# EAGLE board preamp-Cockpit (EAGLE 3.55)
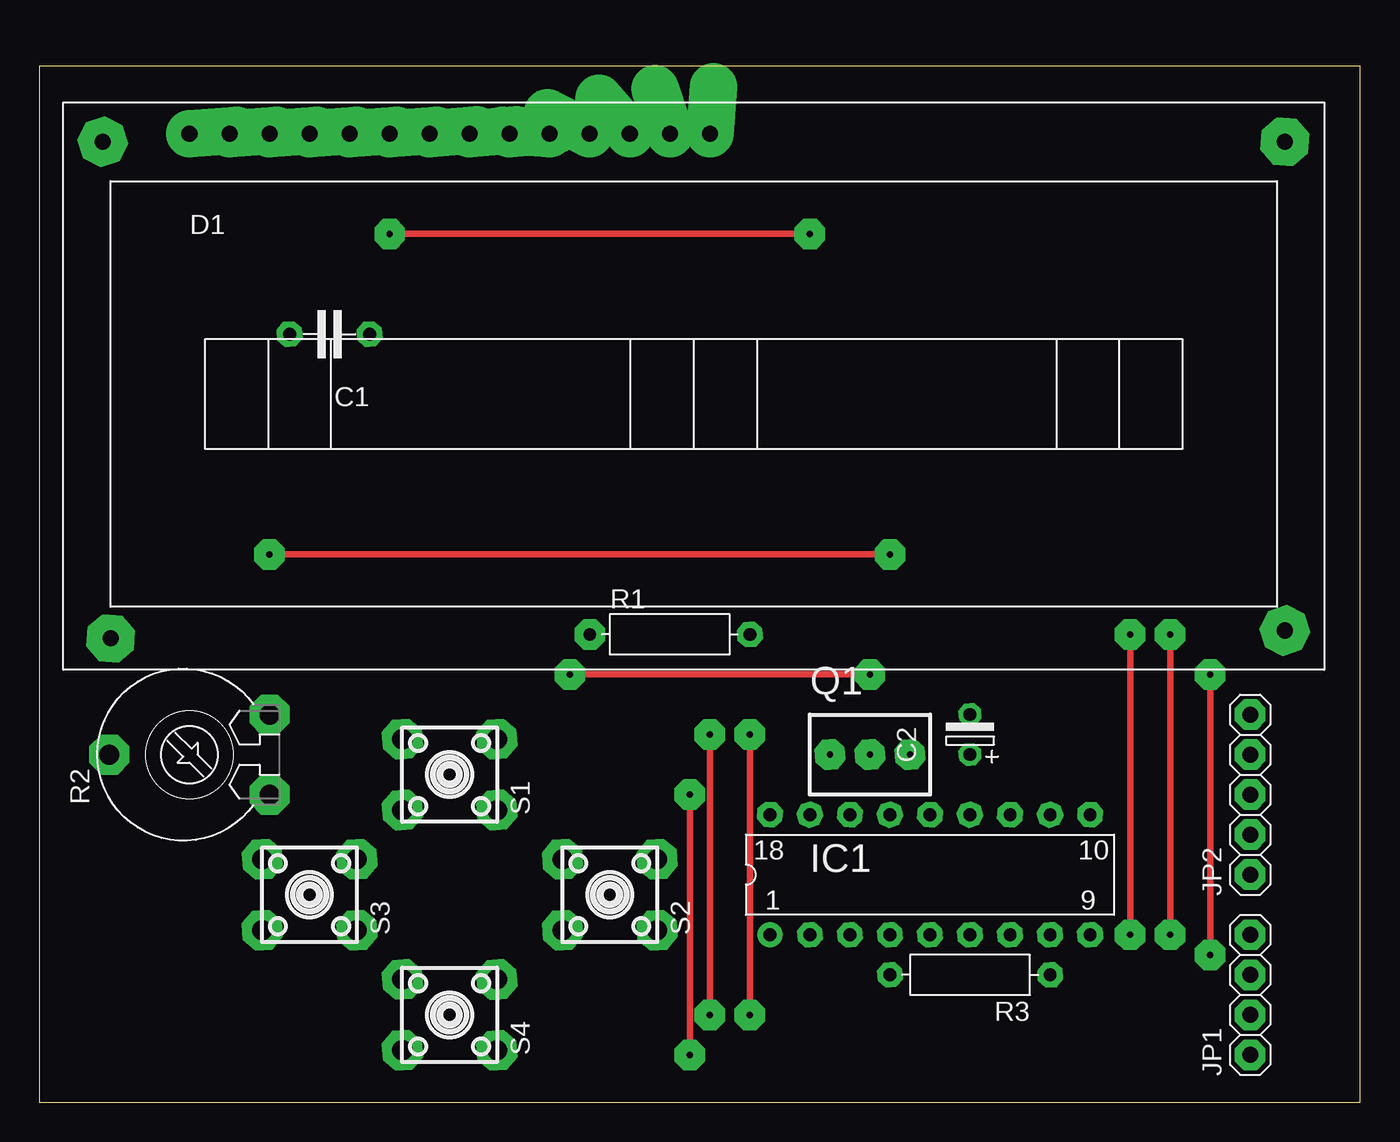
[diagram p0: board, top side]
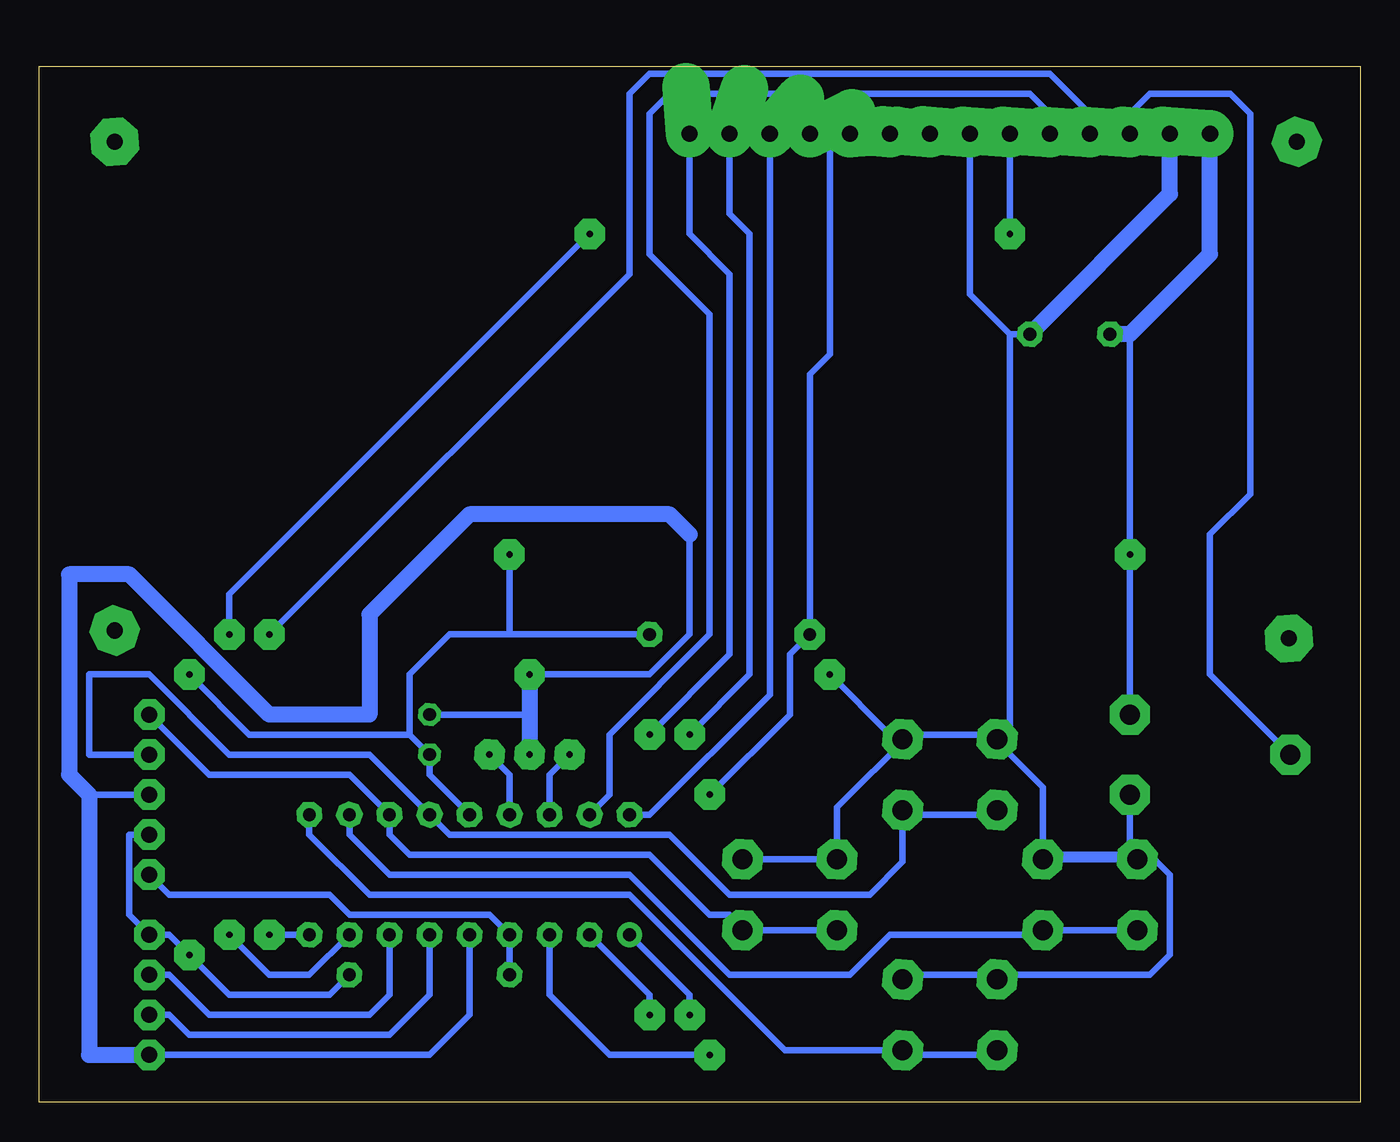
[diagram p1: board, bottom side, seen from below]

Size 83.8 x 65.71 mm. Coordinates in mm from the lower left corner, seen from the top.
Outline: 0,0 83.8,0 83.8,65.71 0,65.71 0,0
Copper layers used: Top, Bottom

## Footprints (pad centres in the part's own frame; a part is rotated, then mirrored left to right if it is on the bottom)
5 = drill 0.813 pad 1.6 octagon:  -2.54,0;  2.54,0
-2,5 = drill 0.813 pad 1.422 octagon:  -1.27,0;  1.27,0
D = drill 1.016 pad 3 octagon:  -5.5,-0.5;  69.5,-0.5;  -5,-32;  69.5,-31.5 | drill 1.016 pad 3 offset:  0,0;  2.54,0;  5.08,0;  7.62,0;  10.16,0;  12.7,0;  15.24,0;  17.78,0;  20.32,0;  22.86,0;  25.4,0;  27.94,0;  30.48,0;  33.02,0
L18 = drill 0.813 pad 1.6 round:  -10.16,-3.81 | drill 0.813 pad 1.6 octagon:  -7.62,-3.81;  -5.08,-3.81;  -2.54,-3.81;  0,-3.81;  2.54,-3.81;  5.08,-3.81;  7.62,-3.81;  10.16,-3.81;  10.16,3.81;  7.62,3.81;  5.08,3.81;  2.54,3.81;  0,3.81;  -2.54,3.81;  -5.08,3.81;  -7.62,3.81;  -10.16,3.81
04 = drill 1.016 pad 1.6 octagon:  -3.81,0;  -1.27,0;  1.27,0;  3.81,0
05 = drill 1.016 pad 1.6 octagon:  -5.08,0;  -2.54,0;  0,0;  2.54,0;  5.08,0
 = drill 0.406 pad 1.93 octagon:  0,0;  -2.54,0;  2.54,0
10 = drill 0.813 pad 1.6 octagon:  -5.08,0;  5.08,0
-10 = drill 1.27 pad 1.778 octagon:  -2.54,-5.08;  2.54,-5.08;  0,5.08
AST = drill 1.27 pad 2.54 octagon:  -2.25,3;  2.25,3;  2.25,-3;  -2.25,-3

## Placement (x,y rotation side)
C1  100n  [5]  18.41,48.73 180 top
C2  10æ  [-2,5]  59.05,23.33 90 top
D1  LCD  [D]  9.52,61.43 0 top
IC1  16F84P  [L18]  56.51,14.44 0 top
JP1  [04]  76.83,6.82 90 top
JP2  ICSP  [05]  76.83,19.52 90 top
Q1  4MHz  []  52.7,22.06 0 top
R1  10k  [10]  40,29.68 0 top
R2  10k  [-10]  9.52,22.06 90 top
R3  10k  [10]  59.05,8.09 180 top
S1  U  [AST]  26.03,20.79 90 top
S2  R  [AST]  36.19,13.17 90 top
S3  L  [AST]  17.14,13.17 90 top
S4  D  [AST]  26.03,5.55 90 top

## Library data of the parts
C1 C2 R1-R3 = DISCRETE
D1 S1-S4 = EIGENE
IC1 = PIC
JP1 JP2 = PINHEAD
Q1 = Spezi

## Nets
3: D1. R2.
4: D1. IC1.
5: D1. IC1. R1.
6: D1. IC1.
11: D1. IC1.
12: D1. IC1.
13: D1. IC1.
14: D1. IC1.
+5V: C1. C2. D1. IC1. JP1. JP2. R1. R2. R3.
GND: C1. C2. D1. IC1. JP1. JP2. Q1. R2. S1. S2. S3. S4.
N$1: IC1. Q1.
N$2: IC1. Q1.
N$3: IC1. JP2. S1.
N$5: IC1. S3.
N$6: IC1. S4.
N$8: IC1. JP2. R3.
N$9: IC1. JP1.
N$10: IC1. JP1.
N$11: IC1. JP2. S2.

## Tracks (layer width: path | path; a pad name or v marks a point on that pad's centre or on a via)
3
  Bottom 0.406: R2. 9.52,27.14 9.52,36.03 6.98,38.57 6.98,62.7 8.25,63.97 13.33,63.97 14.6,62.7 14.6,61.43
4  (via drill 0.41 pad 1.93)
  Top 0.406: v69.21,29.68 v69.21,10.63
  Bottom 0.406: v69.21,10.63 66.67,10.63 | v69.21,29.68 46.35,52.54 46.35,63.97 45.08,65.24 19.68,65.24 17.14,62.7 17.14,61.43
5  (via drill 0.41 pad 1.93)
  Top 0.406: v41.27,3.01 v41.27,19.52
  Bottom 0.406: 51.43,10.63 51.43,6.82 47.62,3.01 v41.27,3.01 | v41.27,19.52 36.19,24.6 36.19,28.41 v34.92,29.68 34.92,46.19 33.65,47.46 33.65,62.7 32.38,63.97 20.95,63.97 19.68,62.7 19.68,61.43
6  (via drill 0.41 pad 1.93)
  Top 0.406: v48.89,55.08 v22.22,55.08 | v71.75,10.63 v71.75,29.68
  Bottom 0.406: v22.22,55.08 22.22,61.43 | v48.89,55.08 71.75,32.22 v71.75,29.68 | v71.75,10.63 69.21,8.09 66.67,8.09 64.13,10.63
11
  Bottom 0.406: 34.92,61.43 34.92,62.7 36.19,63.97 43.81,63.97 45.08,62.7 45.08,53.81 41.27,50 41.27,29.68 47.62,23.33 47.62,19.52 48.89,18.25
12
  Bottom 0.406: 37.46,61.43 37.46,27.14 37.46,25.87 45.08,18.25 IC1.
13  (via drill 0.41 pad 1.93)
  Top 0.406: v42.54,5.55 v42.54,23.33
  Bottom 0.406: 40,61.43 40,56.35 38.73,55.08 38.73,27.14 v42.54,23.33 | 46.35,10.63 42.54,6.82 v42.54,5.55
14  (via drill 0.41 pad 1.93)
  Top 0.406: v45.08,5.55 v45.08,23.33
  Bottom 0.406: D1. 42.54,55.08 40,52.54 40,28.41 v45.08,23.33 | 48.89,10.63 45.08,6.82 v45.08,5.55
+5V  (via drill 0.41 pad 1.93)
  Top 0.406: v74.29,27.14 v74.29,9.36 | v14.6,34.76 v53.97,34.76
  Bottom 0.406: v76.83,16.98 78.1,16.98 78.1,14.44 78.1,11.9 JP1. 75.56,10.63 v74.29,9.36 71.75,6.82 65.4,6.82 64.13,8.09 | 14.6,48.73 v14.6,34.76 14.6,24.6 | 60.32,23.33 59.05,22.06 59.05,20.79 56.51,18.25 | 60.32,23.33 70.48,23.33 v74.29,27.14 | v53.97,34.76 53.97,29.68 | 53.97,29.68 55.24,29.68 | 53.97,29.68 R1. 57.78,29.68 60.32,27.14 60.32,23.33
  Bottom 1.016: 9.52,61.43 9.52,53.81 14.6,48.73 C1.
GND  (via drill 0.41 pad 1.93)
  Top 0.406: v33.65,27.14 v52.7,27.14
  Bottom 0.406: v76.83,3.01 59.05,3.01 56.51,5.55 56.51,10.63 | 80.64,19.52 v76.83,19.52 | 22.22,48.73 24.76,51.27 24.76,61.43 27.3,61.43 29.84,61.43 32.38,61.43 | 22.22,48.73 20.95,48.73 | 23.03,23.04 22.22,23.85 22.22,48.73 | 14.6,19.52 14.6,15.88 14.14,15.42 14.31,15.42 14.6,15.71 | 20.14,15.42 19.85,15.71 14.6,15.71 | 23.03,23.04 23.32,23.33 28.57,23.33 | 29.03,23.04 28.74,23.33 28.57,23.33 | 14.6,15.71 13.33,15.71 12.06,14.44 12.06,9.36 13.33,8.09 22.74,8.09 23.03,7.8 23.32,8.09 28.74,8.09 29.03,7.8 | 20.14,15.42 14.89,15.42 14.6,15.71 | 20.14,15.42 20.14,19.98 23.03,22.87 23.03,23.04 | 28.57,23.33 33.19,18.71 33.19,15.42 38.44,15.42 38.73,15.71 39.02,15.42 39.19,15.42 | 52.7,24.6 v52.7,27.14 45.08,27.14 42.54,29.68 42.54,36.03 | 52.7,24.6 52.7,22.06 | 28.57,23.33 29.84,23.33 v33.65,27.14 | 52.7,24.6 C2.
  Bottom 1.016: v76.83,3.01 80.64,3.01 80.64,19.52 81.91,20.79 81.91,33.49 78.1,33.49 69.21,24.6 62.86,24.6 62.86,30.95 56.51,37.3 43.81,37.3 42.54,36.03 | 12.06,61.43 12.06,57.62 20.95,48.73 | v52.7,27.14 52.7,22.06
N$1
  Bottom 0.406: 51.43,18.25 51.43,20.79 50.16,22.06
N$2
  Bottom 0.406: 53.97,18.25 53.97,20.79 Q1.
N$3  (via drill 0.41 pad 1.93)
  Bottom 0.406: v76.83,22.06 80.64,22.06 80.64,27.14 76.83,27.14 71.75,22.06 62.86,22.06 59.05,18.25 57.78,16.98 43.81,16.98 40,13.17 31.11,13.17 29.03,15.25 S1. 28.74,18.25 23.32,18.25 23.03,18.54
N$4  (via drill 0.41 pad 2.54)
  other vias: 4.44,22.06
N$5
  Bottom 0.406: 64.13,18.25 64.13,16.98 61.59,14.44 46.35,14.44 40,8.09 32.38,8.09 29.84,10.63 20.43,10.63 S3. 19.97,10.92 19.68,10.63 19.39,10.92 14.14,10.92
N$6
  Bottom 0.406: 66.67,18.25 66.67,16.98 62.86,13.17 46.35,13.17 36.48,3.3 S4. 28.74,3.01 23.32,3.01 23.03,3.3
N$7  (via drill 0.41 pad 2.54)
  other vias: 14.6,24.6
N$8
  Bottom 0.406: R3. 53.97,10.63 55.24,11.9 64.13,11.9 65.4,13.17 75.56,13.17 76.83,14.44
N$9
  Bottom 0.406: 76.83,5.55 75.56,5.55 74.29,4.28 61.59,4.28 59.05,6.82 59.05,10.63
N$10
  Bottom 0.406: 76.83,8.09 75.56,8.09 73.02,5.55 62.86,5.55 61.59,6.82 61.59,10.63
N$11
  Bottom 0.406: JP2. 73.02,20.79 64.13,20.79 61.59,18.25 61.59,16.98 60.32,15.71 45.08,15.71 41.27,11.9 40,11.9 38.73,10.63 | 33.19,10.92 38.44,10.92 38.73,10.63 | S2. 39.02,10.92 38.73,10.63
N$12  (via drill 0.41 pad 2.54)
  other vias: 14.6,19.52
N$13  (via drill 0.41 pad 1.93)
  other vias: 76.83,24.6
N$14  (via drill 0.41 pad 1.93)
  other vias: 76.83,10.63
N$15  (via drill 0.41 pad 1.93)
  other vias: 76.83,8.09
N$16  (via drill 0.41 pad 1.93)
  other vias: 76.83,5.55
N$17  (via drill 0.41 pad 1.93)
  other vias: 76.83,14.44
